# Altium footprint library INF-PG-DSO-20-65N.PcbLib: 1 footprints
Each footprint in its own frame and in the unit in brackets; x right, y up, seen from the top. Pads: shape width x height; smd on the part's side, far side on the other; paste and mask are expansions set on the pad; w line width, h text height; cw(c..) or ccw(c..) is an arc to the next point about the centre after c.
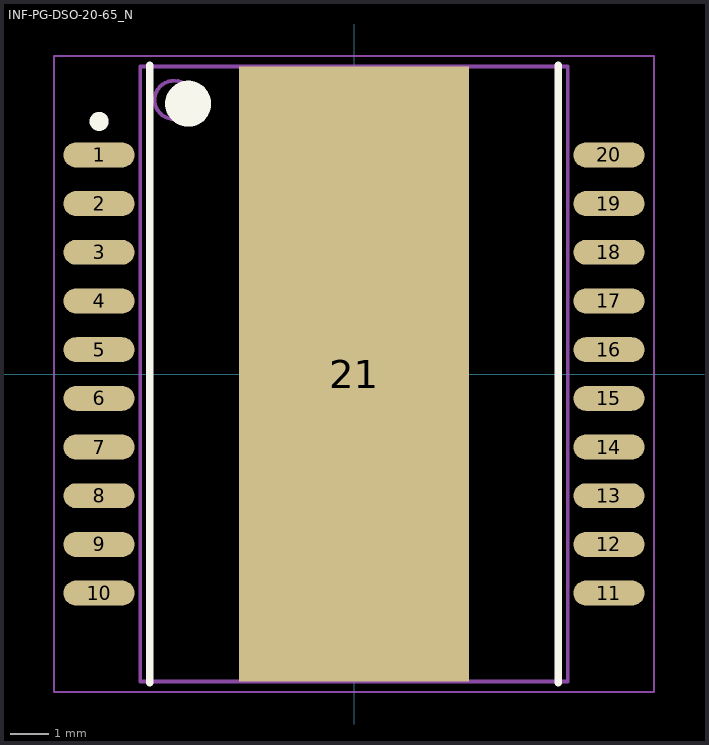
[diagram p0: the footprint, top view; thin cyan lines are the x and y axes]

## INF-PG-DSO-20-65_N [mm] "SOP, 20-Leads, Body 15.9x11mm, Pitch 1.27mm, Thermal Pad 16.05x6mm, IPC Medium Density"
height 3.5
pads (21):
  oval 1.85x0.65 smd: 1(-6.65,5.715) 2(-6.65,4.445) 3(-6.65,3.175) 4(-6.65,1.905) 5(-6.65,0.635) 6(-6.65,-0.635) 7(-6.65,-1.905) 8(-6.65,-3.175) 9(-6.65,-4.445) 10(-6.65,-5.715) 11(6.65,-5.715) 12(6.65,-4.445) 13(6.65,-3.175) 14(6.65,-1.905) 15(6.65,-0.635) 16(6.65,0.635) 17(6.65,1.905) 18(6.65,3.175) 19(6.65,4.445) 20(6.65,5.715)
  rect 6x16.05 smd: 21(0,0)
Top Overlay:
  circle w0.25: c-6.65,6.59 r0.125
  circle w0.6: c-4.325,7.05 r0.3
  lines w0.2: -5.325,-8.05 -5.325,8.05 ; 5.325,-8.05 5.325,8.05
Mechanical 13:
  circle w0.1: c-4.7,7.15 r0.5
  lines w0.1: -5.575,-8.025 -5.575,8.025 5.575,8.025 5.575,-8.025 -5.575,-8.025
Mechanical 15:
  lines w0.05: -7.825,-8.3 -7.825,8.3 7.825,8.3 7.825,-8.3 -7.825,-8.3
  lines w0.1: -0.5,0 0.5,0 ; 0,-0.5 0,0.5
3D body: height 3.5, standoff 0, extent -5.575,-8.025 5.575,8.025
